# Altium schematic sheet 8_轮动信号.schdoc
size 309 x 223 mm; Symbol: Sheet-Symbol_A4; Device: Sheet-Symbol_A4; Company: 嘉立创EDA; Version: V1.0; Page Size: A4; @Project Name: 共享电动车中控; @Page Count: 11; @Update Date: 2024-11-20; @Create Date: 2024-09-26; @Schematic Name: SCH; @Page No: 8; @Page Name: 轮动信号; @Board Name: STM32F103C8T6; @Create Time: 02:39:01; @Update Time: 13:56:36
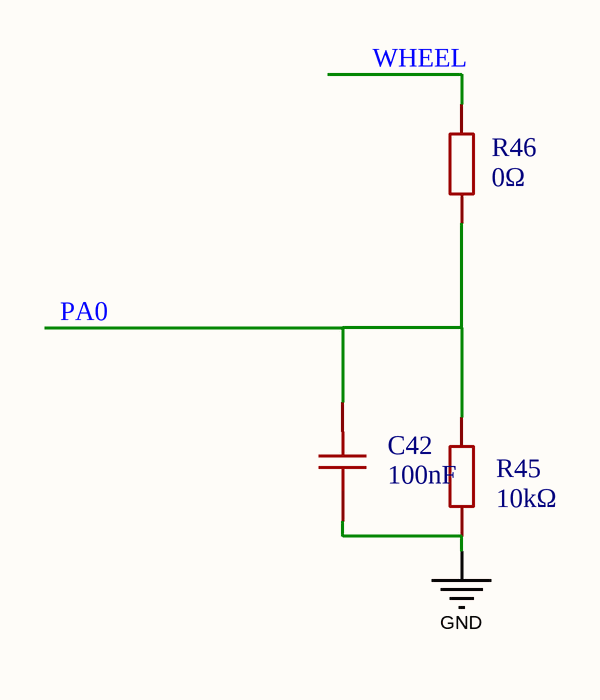
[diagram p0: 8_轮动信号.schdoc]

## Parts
C42  100nF  [C0805]  (value not drawn)
R45  10kΩ  [R0805]
R46  0Ω  [R0603]  (value not drawn)

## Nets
GND: C42.1 R45.2
PA0: C42.2 R45.1 R46.1
WHEEL: R46.2

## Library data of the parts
C42 = CC0805KRX7R9BB104: 容值:100nF;精度:±10%;额定电压:50V;材质(温度系数):X7R;; Manufacturer: YAGEO(国巨); Symbol: CC0603KRX7R9BB104; Add into BOM: yes; Tolerance: ±10%; Voltage Rated: 50V; Temperature Coefficient: X7R
R45 = 0805W8F1002T5E_C17414: 电阻类型:厚膜电阻;阻值:10kΩ;精度:±1%;功率:125mW;最大工作电压:150V;温度系数:±100ppm/℃;; Manufacturer: UNI-ROYAL(厚声); Symbol: RC0402FR-0710KL; Add into BOM: yes; Tolerance: ±1%; Power(Watts): 125mW; Overload Voltage (Max): 150V
R46 = 0603WAF0000T5E: 电阻类型:厚膜电阻;阻值:0Ω;精度:±1%;功率:100mW;最大工作电压:75V;; Manufacturer: UNI-ROYAL(厚声); Add into BOM: yes; Tolerance: ±1%; Power(Watts): 100mW; Overload Voltage (Max): 75V; Temperature Coefficient: ±800ppm/℃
